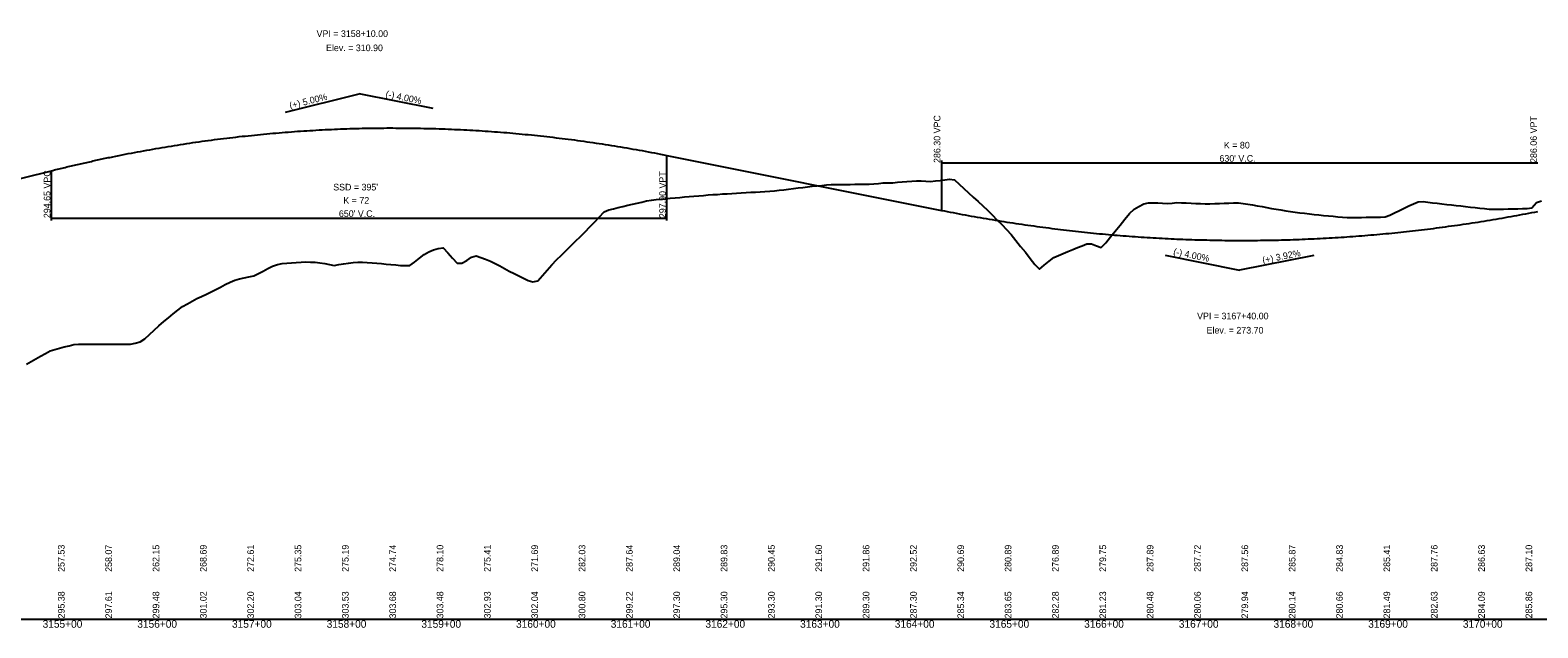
# Model space of a CAD drawing. Extents: x 1838386 to 1955906, y 719739 to 834437.
# Drawn here: x 1952869 to 1954461, y 763480 to 764111 of the extents above; entities that cross this region are included whole.
import ezdxf

# ---------------------------------------------------------------- set-up
doc = ezdxf.new("R2010")
doc.units = 0
for name, color, linetype in [('RD_DDB_GradeTX', 7, 'Continuous'), ('RD_DDB_Profile_EX', 7, 'Continuous'), ('RD_DDB_Profile_Lbl', 7, 'Continuous'), ('RD_DDB_Profile_PR', 7, 'Continuous'), ('RD_DDB_StaTX', 7, 'Continuous'), ('RD_DDB_StripGrade', 7, 'Continuous'), ('RD_DDB_VCLbl', 7, 'Continuous'), ('RD_GPK_Profile_Cell', 7, 'Continuous')]:
    doc.layers.add(name, color=color, linetype=linetype)

msp = doc.modelspace()

# ---------------------------------------------------------------- linework, layer by layer
at = {"layer": 'RD_DDB_GradeTX'}
for p, q in [((1953138.8, 764024.2), (1953216.4, 764043.6)), ((1953294.8, 764028), (1953216.4, 764043.6)), ((1954067.9, 763873.3), (1954146.4, 763857.6)), ((1954224.9, 763873), (1954146.4, 763857.6))]:
    msp.add_line(p, q, dxfattribs=at)
at = {"layer": 'RD_DDB_Profile_EX'}
for points in [[(1953450.1, 763893.1), (1953455.1, 763898.1), (1953460.1, 763903.1), (1953465.1, 763908.1), (1953470.1, 763913.5), (1953475.1, 763919), (1953480.1, 763921.1), (1953485.1, 763922.3), (1953490.1, 763923.5), (1953495.1, 763924.7), (1953500.1, 763925.9), (1953505.1, 763927.1), (1953510.1, 763928.2), (1953515.1, 763929.4), (1953520.1, 763930.6), (1953525.1, 763931.3), (1953530.1, 763931.9), (1953535.1, 763932.3), (1953540.1, 763932.8), (1953545.1, 763933.3), (1953550.1, 763933.8), (1953555.1, 763934.2), (1953560.1, 763934.7), (1953565.1, 763935.1), (1953570.1, 763935.6), (1953575.1, 763936), (1953580.1, 763936.4), (1953585.1, 763936.9), (1953590.1, 763937.2), (1953595.1, 763937.5), (1953600.1, 763937.9), (1953605.1, 763938.2), (1953610.1, 763938.5), (1953615.1, 763938.9), (1953620.1, 763939.1), (1953625.1, 763939.4), (1953630.1, 763939.7), (1953635.1, 763939.9), (1953640.1, 763940.2), (1953645.1, 763940.4), (1953650.1, 763940.7), (1953655.1, 763941.3), (1953660.1, 763941.8), (1953665.1, 763942.4), (1953670.1, 763943), (1953675.1, 763943.6), (1953680.1, 763944.2), (1953685.1, 763944.8), (1953690.1, 763945.4), (1953695.1, 763946), (1953700.1, 763946.6), (1953705.1, 763947), (1953710.1, 763947.4), (1953715.1, 763947.8), (1953720.1, 763947.8), (1953725.1, 763947.8), (1953730.1, 763947.8), (1953735.1, 763947.9), (1953740.1, 763948.1), (1953745.1, 763948.2), (1953750.1, 763948.3), (1953755.1, 763948.4), (1953760.1, 763948.6), (1953765.1, 763948.9), (1953770.1, 763949.6), (1953775.1, 763949.6), (1953780.1, 763949.8), (1953785.1, 763950.2), (1953790.1, 763950.6), (1953795.1, 763951), (1953800.1, 763951.3), (1953805.1, 763951.7), (1953810.1, 763951.9), (1953815.1, 763951.3), (1953820.1, 763951.1), (1953825.1, 763951.6), (1953830.1, 763952.1), (1953835.1, 763952.8), (1953840.1, 763953.5), (1953845.1, 763952.8), (1953850.1, 763948.4), (1953855.1, 763943.7), (1953860.1, 763939.1), (1953865.1, 763934.5), (1953870.1, 763929.9), (1953875.1, 763925.5), (1953880.1, 763920.7), (1953885.1, 763915.8), (1953890.1, 763910.7), (1953895.1, 763905.5), (1953900.1, 763900.4), (1953905.1, 763895.1), (1953910.1, 763888.9), (1953915.1, 763882.6), (1953920.1, 763876.3), (1953925.1, 763869.9), (1953930.1, 763863.6), (1953935.1, 763858.6), (1953940.1, 763862.6), (1953945.1, 763866.8), (1953950.1, 763871)], [(1953950.1, 763871), (1953955.1, 763873.1), (1953960.1, 763875.2), (1953965.1, 763877.3), (1953970.1, 763879.3), (1953975.1, 763881.3), (1953980.1, 763883.2), (1953985.1, 763885.4), (1953990.1, 763885.4), (1953995.1, 763883.3), (1954000.1, 763881.5), (1954005.1, 763886.4), (1954010.1, 763892.5), (1954015.1, 763898.6), (1954020.1, 763905), (1954025.1, 763911.3), (1954030.1, 763917.4), (1954035.1, 763921.7), (1954040.1, 763924.6), (1954045.1, 763927.6), (1954050.1, 763928.4), (1954055.1, 763928.6), (1954060.1, 763928.5), (1954065.1, 763928.2), (1954070.1, 763927.9), (1954075.1, 763928.2), (1954080.1, 763928.8), (1954085.1, 763928.6), (1954090.1, 763928.4), (1954095.1, 763928.2), (1954100.1, 763928), (1954105.1, 763927.8), (1954110.1, 763927.6), (1954115.1, 763927.5), (1954120.1, 763927.7), (1954125.1, 763927.9), (1954130.1, 763928.1), (1954135.1, 763928.3), (1954140.1, 763928.6), (1954145.1, 763928.7), (1954150.1, 763927.9), (1954155.1, 763927.1), (1954160.1, 763926.3), (1954165.1, 763925.4), (1954170.1, 763924.5), (1954175.1, 763923.5), (1954180.1, 763922.6), (1954185.1, 763921.8), (1954190.1, 763921), (1954195.1, 763920.2), (1954200.1, 763919.4), (1954205.1, 763918.6), (1954210.1, 763918.1), (1954215.1, 763917.5), (1954220.1, 763917), (1954225.1, 763916.4), (1954230.1, 763915.7), (1954235.1, 763915.2), (1954240.1, 763914.9), (1954245.1, 763914.4), (1954250.1, 763913.9), (1954255.1, 763913.4), (1954260.1, 763913), (1954265.1, 763912.9), (1954270.1, 763913), (1954275.1, 763913.2), (1954280.1, 763913.3), (1954285.1, 763913.3), (1954290.1, 763913.4), (1954295.1, 763913.5), (1954300.1, 763913.6), (1954305.1, 763915.6), (1954310.1, 763918), (1954315.1, 763920.5), (1954320.1, 763922.9), (1954325.1, 763925.3), (1954330.1, 763927.5), (1954335.1, 763929.7), (1954340.1, 763929.9), (1954345.1, 763929.2), (1954350.1, 763928.7), (1954355.1, 763928.1), (1954360.1, 763927.5), (1954365.1, 763926.9), (1954370.1, 763926.3), (1954375.1, 763925.8), (1954380.1, 763925.3), (1954385.1, 763924.8), (1954390.1, 763924.1), (1954395.1, 763923.6), (1954400.1, 763922.9), (1954405.1, 763922.4), (1954410.1, 763922), (1954415.1, 763921.8), (1954420.1, 763921.9), (1954425.1, 763922), (1954430.1, 763922.2), (1954435.1, 763922.2), (1954440.1, 763922.3), (1954445.1, 763922.4), (1954450.1, 763922.4)], [(1954450.1, 763922.4), (1954455.1, 763923.3), (1954460.1, 763928.8), (1954465.1, 763930.6)], [(1952950.1, 763779.5), (1952955.1, 763779.5), (1952960.1, 763779.5), (1952965.1, 763779.5), (1952970.1, 763779.4), (1952975.1, 763779.4), (1952980.1, 763780.4), (1952985.1, 763781.8), (1952990.1, 763784.9), (1952995.1, 763789.6), (1953000.1, 763794.2), (1953005.1, 763798.8), (1953010.1, 763803.4), (1953015.1, 763807.1), (1953020.1, 763811.3), (1953025.1, 763815.4), (1953030.1, 763819.2), (1953035.1, 763822), (1953040.1, 763824.8), (1953045.1, 763827.5), (1953050.1, 763829.6), (1953055.1, 763832), (1953060.1, 763834.5), (1953065.1, 763837.1), (1953070.1, 763839.7), (1953075.1, 763842.4), (1953080.1, 763844.7), (1953085.1, 763847), (1953090.1, 763848.2), (1953095.1, 763849.3), (1953100.1, 763850.4), (1953105.1, 763851.6), (1953110.1, 763854.1), (1953115.1, 763856.5), (1953120.1, 763859.1), (1953125.1, 763861.8), (1953130.1, 763863.4), (1953135.1, 763864.5), (1953140.1, 763864.7), (1953145.1, 763865.1), (1953150.1, 763865.4), (1953155.1, 763865.8), (1953160.1, 763866.1), (1953165.1, 763866), (1953170.1, 763865.8), (1953175.1, 763865.3), (1953180.1, 763864.6), (1953185.1, 763863.6), (1953190.1, 763862.4), (1953195.1, 763863.3), (1953200.1, 763864.2), (1953205.1, 763864.9), (1953210.1, 763865.5), (1953215.1, 763865.8), (1953220.1, 763866), (1953225.1, 763865.7), (1953230.1, 763865.3), (1953235.1, 763864.8), (1953240.1, 763864.4), (1953245.1, 763863.9), (1953250.1, 763863.4), (1953255.1, 763863), (1953260.1, 763862.5), (1953265.1, 763862.5), (1953270.1, 763862.4), (1953275.1, 763865.9), (1953280.1, 763870), (1953285.1, 763874.1), (1953290.1, 763876.7), (1953295.1, 763879.1), (1953300.1, 763880.2), (1953305.1, 763881), (1953310.1, 763875.6), (1953315.1, 763870.3), (1953320.1, 763865), (1953325.1, 763865), (1953330.1, 763867.8), (1953335.1, 763871.3), (1953340.1, 763872.7), (1953345.1, 763871), (1953350.1, 763869.1), (1953355.1, 763866.8), (1953360.1, 763864.4), (1953365.1, 763861.9), (1953370.1, 763859.2), (1953375.1, 763856.5), (1953380.1, 763854.1), (1953385.1, 763851.4), (1953390.1, 763849), (1953395.1, 763846.7), (1953400.1, 763845.3), (1953405.1, 763846.2), (1953410.1, 763851.8), (1953415.1, 763857.4), (1953420.1, 763863), (1953425.1, 763868.4), (1953430.1, 763873.3), (1953435.1, 763878.2), (1953440.1, 763883.1), (1953445.1, 763888.1), (1953450.1, 763893.1)], [(1952865.1, 763758.3), (1952870.1, 763761.1), (1952875.1, 763763.9), (1952880.1, 763766.8), (1952885.1, 763769.6), (1952890.1, 763772.4), (1952895.1, 763773.9), (1952900.1, 763775.2), (1952905.1, 763776.5), (1952910.1, 763777.7), (1952915.1, 763779), (1952920.1, 763779.4), (1952925.1, 763779.4), (1952930.1, 763779.5), (1952935.1, 763779.5), (1952940.1, 763779.5), (1952945.1, 763779.5), (1952950.1, 763779.5)]]:
    msp.add_lwpolyline(points, dxfattribs=at)
at = {"layer": 'RD_DDB_Profile_PR'}
for p, q in [((1953541.4, 763978.6), (1953831.4, 763920.6)), ((1952321.4, 763819.9), (1952891.4, 763962.4))]:
    msp.add_line(p, q, dxfattribs=at)
for points in [[(1952891.4, 763962.4), (1952904.4, 763965.6), (1952917.4, 763968.7), (1952930.4, 763971.6), (1952943.4, 763974.5), (1952956.4, 763977.2), (1952969.4, 763979.8), (1952982.4, 763982.3), (1952995.4, 763984.6), (1953008.4, 763986.9), (1953021.4, 763989), (1953034.4, 763991.1), (1953047.4, 763993), (1953060.4, 763994.8), (1953073.4, 763996.4), (1953086.4, 763998), (1953099.4, 763999.4), (1953112.4, 764000.7), (1953125.4, 764001.9), (1953138.4, 764003), (1953151.4, 764004), (1953164.4, 764004.8), (1953177.4, 764005.6), (1953190.4, 764006.2), (1953203.4, 764006.7), (1953216.4, 764007.1), (1953229.4, 764007.3), (1953242.4, 764007.5), (1953255.4, 764007.5), (1953268.4, 764007.4), (1953281.4, 764007.2), (1953294.4, 764006.9), (1953307.4, 764006.5), (1953320.4, 764005.9), (1953333.4, 764005.3), (1953346.4, 764004.5), (1953359.4, 764003.6), (1953372.4, 764002.6), (1953385.4, 764001.4), (1953398.4, 764000.2), (1953411.4, 763998.8), (1953424.4, 763997.3), (1953437.4, 763995.7), (1953450.4, 763994), (1953463.4, 763992.1), (1953476.4, 763990.2), (1953489.4, 763988.1), (1953502.4, 763985.9), (1953515.4, 763983.6), (1953528.4, 763981.2), (1953541.4, 763978.6)], [(1953831.4, 763920.6), (1953844, 763918.2), (1953856.6, 763915.8), (1953869.2, 763913.5), (1953881.8, 763911.4), (1953894.4, 763909.3), (1953907, 763907.3), (1953919.6, 763905.4), (1953932.2, 763903.7), (1953944.8, 763902), (1953957.4, 763900.4), (1953970, 763899), (1953982.6, 763897.6), (1953995.2, 763896.3), (1954007.8, 763895.1), (1954020.4, 763894.1), (1954033, 763893.1), (1954045.6, 763892.2), (1954058.2, 763891.5), (1954070.8, 763890.8), (1954083.4, 763890.2), (1954096, 763889.7), (1954108.6, 763889.4), (1954121.2, 763889.1), (1954133.8, 763888.9), (1954146.4, 763888.8), (1954159, 763888.9), (1954171.6, 763889), (1954184.2, 763889.2), (1954196.8, 763889.5), (1954209.4, 763890), (1954222, 763890.5), (1954234.6, 763891.1), (1954247.2, 763891.8), (1954259.8, 763892.7), (1954272.4, 763893.6), (1954285, 763894.6), (1954297.6, 763895.7), (1954310.2, 763897), (1954322.8, 763898.3), (1954335.4, 763899.7), (1954348, 763901.2), (1954360.6, 763902.9), (1954373.2, 763904.6), (1954385.8, 763906.4), (1954398.4, 763908.3), (1954411, 763910.3), (1954423.6, 763912.5), (1954436.2, 763914.7), (1954448.8, 763917), (1954461.4, 763919.4)]]:
    msp.add_spline(points, degree=3, dxfattribs=at)
at = {"layer": 'RD_DDB_VCLbl'}
for p, q in [((1953541.4, 763909.9), (1953541.4, 763978.6)), ((1952891.4, 763909.9), (1952891.4, 763962.4)), ((1953831.4, 763973.1), (1953831.4, 763920.6)), ((1953831.4, 763970.6), (1954461.4, 763970.6)), ((1952891.4, 763912.4), (1953541.4, 763912.4))]:
    msp.add_line(p, q, dxfattribs=at)
at = {"layer": 'RD_GPK_Profile_Cell'}
msp.add_line((1951406.4, 763489.1), (1955506.4, 763489.1), dxfattribs=at)

# ---------------------------------------------------------------- texts
at = {"layer": 'RD_DDB_GradeTX'}
for s, rotation, p in [('(+) 5.00%', 14.0362, (1953143.8, 764027.6)), ('(-) 4.00%', 348.6901, (1953243.9, 764040.2)), ('(-) 4.00%', 348.6901, (1954075.9, 763873.8)), ('(+) 3.92%', 11.0973, (1954171.2, 763864.5))]:
    msp.add_text(s, height=7, rotation=rotation, dxfattribs=at).set_placement(p)
at = {"layer": 'RD_DDB_Profile_Lbl'}
for s, p in [('VPI = 3158+10.00', (1953171.5, 764103.6)), ('Elev. = 310.90', (1953181.5, 764088.6)), ('VPI = 3167+40.00', (1954101.5, 763805.6)), ('Elev. = 273.70', (1954111.5, 763790.6))]:
    msp.add_text(s, height=7, dxfattribs=at).set_placement(p)
at = {"layer": 'RD_DDB_StaTX'}
for s, p in [('3155+00', (1952882.2, 763480.1)), ('3156+00', (1952982.2, 763480.1)), ('3157+00', (1953082.2, 763480.1)), ('3158+00', (1953182.2, 763480.1)), ('3159+00', (1953282.2, 763480.1)), ('3160+00', (1953382.2, 763480.1)), ('3161+00', (1953482.2, 763480.1)), ('3162+00', (1953582.2, 763480.1)), ('3163+00', (1953682.2, 763480.1)), ('3164+00', (1953782.2, 763480.1)), ('3165+00', (1953882.2, 763480.1)), ('3166+00', (1953982.2, 763480.1)), ('3167+00', (1954082.2, 763480.1)), ('3168+00', (1954182.2, 763480.1)), ('3169+00', (1954282.2, 763480.1)), ('3170+00', (1954382.2, 763480.1))]:
    msp.add_text(s, height=8, dxfattribs=at).set_placement(p)
at = {"layer": 'RD_DDB_StripGrade'}
for s, p in [('286.30 VPC', (1953830.4, 763970.6)), ('286.06 VPT', (1954460.4, 763970.6)), ('294.65 VPC', (1952890.4, 763912.4)), ('297.90 VPT', (1953540.4, 763912.4)), ('257.53', (1952905.4, 763539.1)), ('258.07', (1952955.4, 763539.1)), ('262.15', (1953005.4, 763539.1)), ('268.69', (1953055.4, 763539.1)), ('272.61', (1953105.4, 763539.1)), ('275.35', (1953155.4, 763539.1)), ('275.19', (1953205.4, 763539.1)), ('274.74', (1953255.4, 763539.1)), ('278.10', (1953305.4, 763539.1)), ('275.41', (1953355.4, 763539.1)), ('271.69', (1953405.4, 763539.1)), ('282.03', (1953455.4, 763539.1)), ('287.64', (1953505.4, 763539.1)), ('289.04', (1953555.4, 763539.1)), ('289.83', (1953605.4, 763539.1)), ('290.45', (1953655.4, 763539.1)), ('291.60', (1953705.4, 763539.1)), ('291.86', (1953755.4, 763539.1)), ('292.52', (1953805.4, 763539.1)), ('290.69', (1953855.4, 763539.1)), ('280.89', (1953905.4, 763539.1)), ('276.89', (1953955.4, 763539.1)), ('279.75', (1954005.4, 763539.1)), ('287.89', (1954055.4, 763539.1)), ('287.72', (1954105.4, 763539.1)), ('287.56', (1954155.4, 763539.1)), ('285.87', (1954205.4, 763539.1)), ('284.83', (1954255.4, 763539.1)), ('285.41', (1954305.4, 763539.1)), ('287.76', (1954355.4, 763539.1)), ('286.63', (1954405.4, 763539.1)), ('287.10', (1954455.4, 763539.1)), ('295.38', (1952905.4, 763489.9)), ('297.61', (1952955.4, 763489.9)), ('299.48', (1953005.4, 763489.9)), ('301.02', (1953055.4, 763489.9)), ('302.20', (1953105.4, 763489.9)), ('303.04', (1953155.4, 763489.9)), ('303.53', (1953205.4, 763489.9)), ('303.68', (1953255.4, 763489.9)), ('303.48', (1953305.4, 763489.9)), ('302.93', (1953355.4, 763489.9)), ('302.04', (1953405.4, 763489.9)), ('300.80', (1953455.4, 763489.9)), ('299.22', (1953505.4, 763489.9)), ('297.30', (1953555.4, 763489.9)), ('295.30', (1953605.4, 763489.9)), ('293.30', (1953655.4, 763489.9)), ('291.30', (1953705.4, 763489.9)), ('289.30', (1953755.4, 763489.9)), ('287.30', (1953805.4, 763489.9)), ('285.34', (1953855.4, 763489.9)), ('283.65', (1953905.4, 763489.9)), ('282.28', (1953955.4, 763489.9)), ('281.23', (1954005.4, 763489.9)), ('280.48', (1954055.4, 763489.9)), ('280.06', (1954105.4, 763489.9)), ('279.94', (1954155.4, 763489.9)), ('280.14', (1954205.4, 763489.9)), ('280.66', (1954255.4, 763489.9)), ('281.49', (1954305.4, 763489.9)), ('282.63', (1954355.4, 763489.9)), ('284.09', (1954405.4, 763489.9)), ('285.86', (1954455.4, 763489.9))]:
    msp.add_text(s, height=7, rotation=90, dxfattribs=at).set_placement(p)
at = {"layer": 'RD_DDB_VCLbl'}
for s, p in [("630' V.C.", (1954125.1, 763971.9)), ('K = 80', (1954129.8, 763985.9)), ("SSD = 395'", (1953189.1, 763941.6)), ('K = 72', (1953199.8, 763927.6)), ("650' V.C.", (1953195.1, 763913.6))]:
    msp.add_text(s, height=7, dxfattribs=at).set_placement(p)

doc.saveas('drawing.dxf')
